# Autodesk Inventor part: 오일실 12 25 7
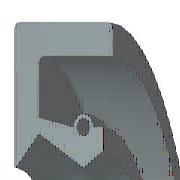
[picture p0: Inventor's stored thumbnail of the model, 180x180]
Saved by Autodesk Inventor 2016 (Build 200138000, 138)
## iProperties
IsCustomPart: 1
Created: 2012-02
Part Number: 오일실 12 25 7
Material: 고무
Description: 오일-실
Document SubType Name: Modeling
Standard: KS B 2804
Designer: test
Standards Organization: KS
Language: ko-KR
Size Designation: D - 12 25 7
Categories: <MemberInstance><Categories><Category DisplayName="샤프트 부품" InternalName="7f7aeb1f-a693-4053-b835-cee3144e0d98" Mnemonic="SHFT"><Category DisplayName="실링" Intern
Density: 0.93 g/cm^3
Appearance: 고무 - 검은색 - 버전 1.1
Author: test
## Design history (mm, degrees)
revolve "본체" stored, may be unused: angle "d17" = 90 deg
revolve "스프링1" stored, may be unused: angle "d18" = 90 deg
body "Solid1"
sketch "스케치1"
  geometry: L1 (0, 12.5)-(7, 12.5); L2 (7, 10.75)-(1.75, 10.75); L3 (1.75, 7.75)-(4.9, 6); L4 (4.9, 6)-(0, 6); L5 (0, 0)-(9.586, 0) reference; L6 (4.9, 6)-(6.3, 6.875); L7 (0, 18)-(0, -3) reference; L8 (-1.941, 0)-(11.507, 0) reference; L9 (4.2, 8.1)-(1.75, 8.59); L10 (1.75, 8.59)-(1.75, 10.75); L11 (0, 12.5)-(0, 6.088); L12 (4.9, 6)-(0, 6); L13 (1.75, 7.75)-(0.152, 6.028); L14 (7, 12.5)-(7, 10.75); L15 (5.6, 8.1)-(6.3, 8.1); L16 (6.3, 8.1)-(6.3, 6.875); C1 r 0.455 at (4.9, 8.1); A1 r 0.7 centre (4.9, 8.1) between (5.6, 8.1) and (4.2, 8.1); A2 r 0.088 centre (0.088, 6.088) between (0, 6.088) and (0.152, 6.028); 1 further point
  constraints: 28 end point, 5 horizontal alignment, 5 point on line, 4 point on circle, 4 vertical alignment, 3 centre point, 3 tangent, 2 collinear, 2 horizontal, 2 perpendicular, 1 coincident, 1 parallel
  dimensions: "d0" = 25 diameter of L1 L5 (= SD2); "d1" = 1.75 distance of L1.end L2.start (= SD); "d2" = 0.91 diameter of C1 (= SPDI); "d3" = 1.4 diameter of A1 (= SPDA); "d4" = 12 diameter of L3.end L5 (= NND); "d5" = 15.5 diameter of L3.start L5 (= TKDM); "d7" = 17.18 diameter of L9.end L5 (= TKDM + 0.24 x SWDT); "d8" = 1.75 distance between parallel lines of L11 L10 (= SD); "d9" = 4.9 distance from line of L11 C1.centre (= SPDST); "d10" = 16.2 diameter of C1.centre L5 (= HLDM); "d11" = 0.0875 radius of A2 (= 0.25 x LAB); "d12" = 6.3 distance between parallel lines of L11 L16 (= SDI); "d13" = 13.75 diameter of L6.end L5 (= ABDM); "d14" = 7 distance from line of L11 L1.end (= SWDT)
fillet "모깎기1" dims "d6" = 0.3 (= RR)
other parameters: "SD2" = 25 [user parameter; used in 1 equation term], "SWDT" = 7 [user parameter; used in 2 equation terms], "RR" = 0.3 [user parameter; used in 1 equation term], "SD" = 1.75 [user parameter; used in 2 equation terms], "NND" = 12 [user parameter; used in 1 equation term], "SPDA" = 1.4 [user parameter; used in 1 equation term], "SPDI" = 0.91 [user parameter; used in 1 equation term], "TKDM" = 15.5 [user parameter; used in 2 equation terms], "HLDM" = 16.2 [user parameter; used in 1 equation term], "ABDM" = 13.75 [user parameter; used in 1 equation term], "SDI" = 6.3 [user parameter; used in 1 equation term], "SPDST" = 4.9 [user parameter; used in 1 equation term], "LAB" = 0.35 [user parameter; used in 1 equation term], "d15" = 0, "d16" = 0, "d19" = 0
